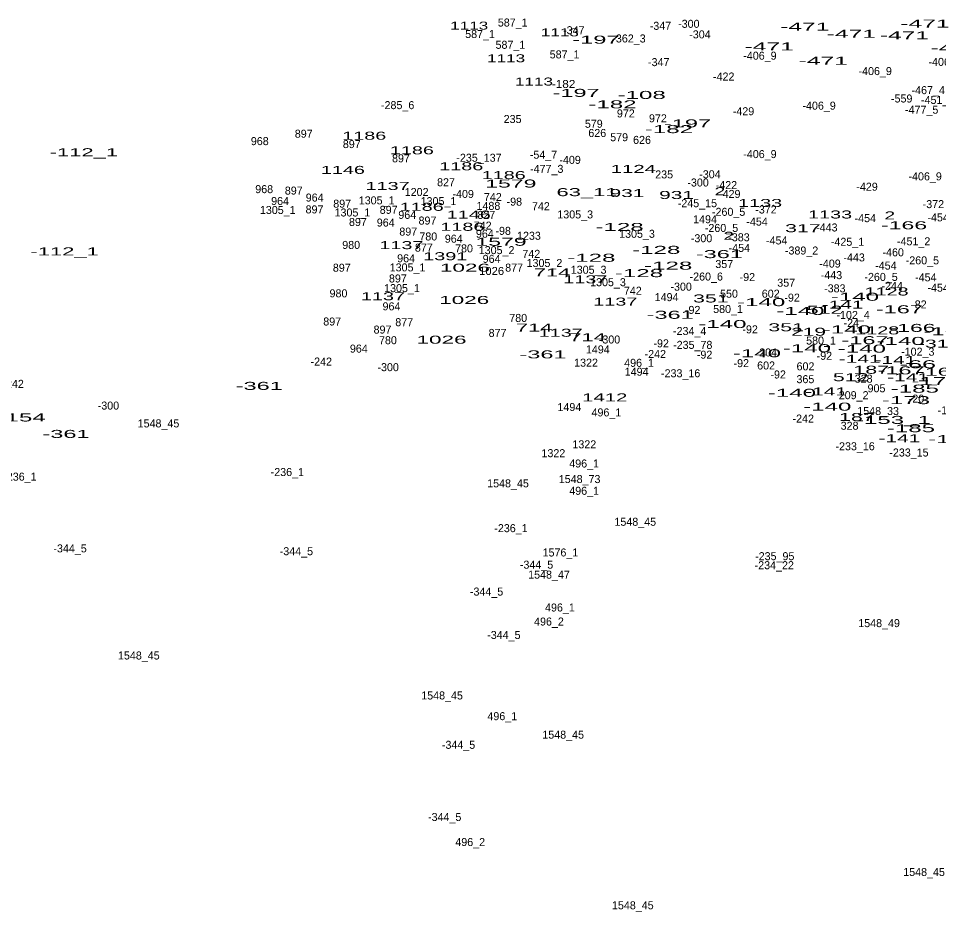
# Model space of a CAD drawing. Extents: x -660434 to -656144, y -997850 to -994016.
# Drawn here: x -659474 to -659014.2, y -996076.3 to -995629.8 of the extents above; entities that cross this region are included whole.
import ezdxf
from ezdxf.enums import TextEntityAlignment as Align

# ---------------------------------------------------------------- set-up
doc = ezdxf.new("R2010")
doc.units = 0
doc.header["$LTSCALE"] = 1.6
doc.layers.add('24', color=7, linetype='Continuous')

msp = doc.modelspace()

# ---------------------------------------------------------------- texts
at = {"layer": '24'}
for s, width, p in [('1113', 1.6, (-659248.79, -995635.4)), ('-471', 2.3, (-659081.121, -995635.93)), ('-471', 2.3, (-659021.021, -995634.39)), ('1113', 1.6, (-659203.48, -995638.76)), ('-471', 2.3, (-659057.831, -995639.5)), ('-471', 2.3, (-659031.331, -995640.26)), ('-197', 2.2, (-659185.479, -995642.42)), ('-471', 2.3, (-659098.881, -995645.83)), ('-471', 2.3, (-659005.981, -995646.6)), ('1113', 1.6, (-659230.36, -995651.72)), ('-471', 2.3, (-659071.841, -995652.94)), ('1113', 1.6, (-659216.44, -995663.35)), ('-182', 1.1, (-659201.63, -995664.56)), ('-197', 2.2, (-659195.369, -995669.02)), ('-108', 2.25, (-659162.587, -995670.05)), ('-182', 2.25, (-659177.191, -995674.74)), ('-182', 2.25, (-659148.971, -995687.12)), ('-197', 2.2, (-659139.689, -995684.28)), ('1186', 1.85, (-659301.239, -995690.43)), ('-112_1', 2.05, (-659441.334, -995698.7)), ('1186', 1.85, (-659277.429, -995697.72)), ('1146', 1.85, (-659311.905, -995707.52)), ('1186', 1.85, (-659252.759, -995705.69)), ('1186', 1.85, (-659231.539, -995710.12)), ('1124', 1.9, (-659166.759, -995707.02)), ('1579', 2.15, (-659227.997, -995714.34)), ('1137', 1.85, (-659289.579, -995715.54)), ('63_11', 2.05, (-659189.91, -995718.63)), ('931', 1.95, (-659169.943, -995719.09)), ('2', 1.8, (-659123.511, -995718.18)), ('931', 1.95, (-659145.183, -995720.05)), ('1186', 1.85, (-659272.529, -995725.97)), ('1133', 1.85, (-659103.424, -995724.04)), ('1146', 1.85, (-659249.005, -995729.84)), ('1133', 1.85, (-659068.474, -995729.8)), ('2', 1.8, (-659038.641, -995730.28)), ('1186', 1.85, (-659252.179, -995735.96)), ('-128', 2.25, (-659173.641, -995736.06)), ('317', 2, (-659082.043, -995736.65)), ('-166', 2.15, (-659031.479, -995735.21)), ('2', 1.8, (-659119.101, -995740.46)), ('1137', 1.85, (-659282.669, -995745.12)), ('1579', 2.15, (-659232.887, -995743.44)), ('-112_1', 2.05, (-659450.934, -995748.25)), ('1391', 1.85, (-659260.759, -995750.66)), ('-128', 2.25, (-659187.761, -995751.43)), ('-128', 2.25, (-659155.311, -995747.49)), ('-361', 2.2, (-659123.775, -995749.6)), ('-128', 2.25, (-659149.351, -995755.37)), ('1026', 2.1, (-659250.909, -995756.4)), ('1026', 1.05, (-659237.591, -995758.03)), ('714', 2.05, (-659207.388, -995758.78)), ('-128', 2.25, (-659163.951, -995759.11)), ('1137', 1.85, (-659190.749, -995762.21)), ('1128', 1.85, (-659040.234, -995768.29)), ('1137', 1.85, (-659291.879, -995770.66)), ('1026', 2.1, (-659251.289, -995772.53)), ('1137', 1.85, (-659175.779, -995773.35)), ('351', 2, (-659128.027, -995771.78)), ('-140', 2.25, (-659102.882, -995773.61)), ('-140', 2.25, (-659056.032, -995770.92)), ('-140', 2.25, (-659083.302, -995778.03)), ('512', 2, (-659071.197, -995777.41)), ('-141', 1.95, (-659062.202, -995774.88)), ('-167', 2.2, (-659033.809, -995777.18)), ('-361', 2.2, (-659148.345, -995779.94)), ('714', 2.05, (-659216.318, -995786.35)), ('-140', 2.25, (-659122.272, -995784.56)), ('351', 2, (-659090.397, -995786.18)), ('-140', 2.25, (-659060.062, -995787.25)), ('1128', 1.85, (-659044.894, -995787.74)), ('-166', 2.15, (-659027.249, -995786.5)), ('-163', 2.2, (-659009.915, -995788.14)), ('1026', 2.1, (-659262.619, -995792.39)), ('1137', 1.85, (-659203.039, -995788.91)), ('714', 2.05, (-659189.628, -995791.15)), ('219', 1.95, (-659079.203, -995788.42)), ('-167', 2.2, (-659050.999, -995792.64)), ('-140', 2.25, (-659080.032, -995796.66)), ('-140', 2.25, (-659052.582, -995796.85)), ('-140', 2.25, (-659033.182, -995793.01)), ('-31', 2, (-659016.931, -995794.37)), ('-361', 2.2, (-659211.905, -995799.73)), ('-140', 2.25, (-659104.992, -995799.15)), ('-141', 1.95, (-659053.662, -995801.95)), ('-141', 1.95, (-659035.802, -995802.54)), ('-66', 2.35, (-659024.583, -995804.66)), ('512', 2, (-659058.137, -995811.13)), ('187', 2, (-659047.893, -995807.41)), ('-167', 2.2, (-659032.949, -995807.72)), ('-141', 1.95, (-659029.472, -995811.17)), ('-166', 2.15, (-659013.429, -995808.39)), ('-361', 2.2, (-659353.685, -995815.48)), ('-173', 2.25, (-659015.755, -995813.08)), ('-140', 2.25, (-659087.522, -995818.94)), ('-141', 1.95, (-659070.462, -995818.28)), ('-185', 2.25, (-659026.111, -995816.84)), ('1412', 1.9, (-659181.039, -995821.24)), ('-173', 2.25, (-659030.535, -995822.59)), ('-140', 2.25, (-659069.862, -995825.85)), ('-154', 2.25, (-659472.426, -995831.25)), ('187', 2, (-659055.083, -995831.04)), ('-153_1', 2.25, (-659036.797, -995832.48)), ('-185', 2.25, (-659028.031, -995836.62)), ('-361', 2.2, (-659450.265, -995839.49)), ('-141', 1.95, (-659033.792, -995841.62)), ('-173', 2.25, (-659007.395, -995842.09))]:
    msp.add_text(s, height=4, dxfattribs=dict(at, width=width)).set_placement(p, align=Align.CENTER)
for s, p in [('587_1', (-659227.044, -995633.85)), ('-347', (-659153.215, -995635.5)), ('-300', (-659139.043, -995634.49)), ('587_1', (-659243.364, -995639.61)), ('-347', (-659196.515, -995637.7)), ('-304', (-659133.493, -995639.78)), ('587_1', (-659228.194, -995644.99)), ('-362_3', (-659168.948, -995641.82)), ('587_1', (-659201.124, -995649.79)), ('-347', (-659154.085, -995653.65)), ('-406_9', (-659103.512, -995650.44)), ('-406_9', (-659010.962, -995653.51)), ('-406_9', (-659045.912, -995658.12)), ('-422', (-659121.599, -995660.85)), ('-467_4', (-659019.422, -995667.65)), ('-559', (-659032.67, -995671.82)), ('-451_3', (-659014.7, -995672.54)), ('-285_6', (-659284.548, -995675.14)), ('-406_9', (-659073.942, -995675.41)), ('-477_5', (-659022.688, -995677.43)), ('235', (-659227.107, -995682.08)), ('972', (-659170.528, -995679.28)), ('972', (-659154.488, -995681.73)), ('-429', (-659111.725, -995678.19)), ('579', (-659186.538, -995684.45)), ('897', (-659331.468, -995689.43)), ('626', (-659184.798, -995689.06)), ('579', (-659173.868, -995691.17)), ('968', (-659353.438, -995693.13)), ('897', (-659307.468, -995694.62)), ('626', (-659162.428, -995692.52)), ('-54_7', (-659211.652, -995699.92)), ('-406_9', (-659103.512, -995699.61)), ('897', (-659282.888, -995701.73)), ('-235_137', (-659243.911, -995701.44)), ('-409', (-659198.379, -995702.5)), ('-477_3', (-659210.048, -995707)), ('235', (-659151.367, -995709.77)), ('-304', (-659128.503, -995709.7)), ('827', (-659260.373, -995713.68)), ('-300', (-659134.423, -995713.82)), ('-406_9', (-659020.952, -995710.75)), ('968', (-659351.238, -995717.14)), ('897', (-659336.458, -995717.86)), ('1202', (-659275.054, -995718.58)), ('-422', (-659120.259, -995715.1)), ('-429', (-659049.985, -995715.93)), ('964', (-659343.303, -995723.08)), ('964', (-659326.023, -995721.35)), ('1305_1', (-659295.046, -995722.75)), ('1305_1', (-659264.136, -995723.14)), ('-409', (-659251.799, -995719.55)), ('742', (-659236.967, -995721.06)), ('-98', (-659226.24, -995723.39)), ('-429', (-659118.585, -995719.53)), ('1305_1', (-659344.456, -995727.55)), ('897', (-659326.088, -995727.27)), ('897', (-659312.268, -995724.39)), ('897', (-659289.038, -995727.47)), ('1488', (-659239.194, -995725.5)), ('742', (-659212.967, -995725.67)), ('-245_15', (-659134.759, -995724.16)), ('-260_5', (-659119.152, -995728.47)), ('-372', (-659100.501, -995727.31)), ('-372', (-659016.841, -995724.62)), ('1305_1', (-659307.136, -995728.8)), ('964', (-659279.743, -995730)), ('897', (-659269.638, -995732.84)), ('827', (-659240.213, -995730)), ('1305_3', (-659195.833, -995729.77)), ('1494', (-659130.954, -995732.18)), ('-454', (-659050.853, -995731.63)), ('-454', (-659014.463, -995731.25)), ('897', (-659304.398, -995733.55)), ('964', (-659290.503, -995733.84)), ('742', (-659242.057, -995735.37)), ('-260_5', (-659122.712, -995736.53)), ('-454', (-659104.953, -995733.36)), ('-443', (-659070.083, -995736.29)), ('897', (-659279.238, -995738.35)), ('780', (-659269.237, -995740.79)), ('964', (-659256.513, -995741.91)), ('964', (-659240.963, -995739.41)), ('-98', (-659231.81, -995737.99)), ('1233', (-659218.94, -995740.44)), ('1305_3', (-659164.943, -995739.45)), ('-300', (-659132.693, -995741.68)), ('-383', (-659113.985, -995741.19)), ('980', (-659307.777, -995745.02)), ('877', (-659271.469, -995746.37)), ('780', (-659251.377, -995746.74)), ('-454', (-659113.793, -995746.52)), ('-454', (-659095.133, -995742.78)), ('-425_1', (-659059.73, -995743.45)), ('-451_2', (-659026.7, -995743.21)), ('1305_2', (-659235.093, -995747.63)), ('742', (-659217.757, -995749.49)), ('-389_2', (-659082.698, -995747.81)), ('-443', (-659056.453, -995751.27)), ('-460', (-659036.919, -995748.7)), ('964', (-659280.323, -995751.7)), ('964', (-659237.603, -995751.99)), ('1305_2', (-659211.193, -995754.06)), ('357', (-659121.333, -995754.56)), ('-409', (-659068.499, -995754.34)), ('-454', (-659040.573, -995755.35)), ('-260_5', (-659022.342, -995752.73)), ('897', (-659312.458, -995756.41)), ('1305_1', (-659279.596, -995756.25)), ('877', (-659226.349, -995756.36)), ('1305_3', (-659189.113, -995757.42)), ('-443', (-659067.783, -995760.11)), ('897', (-659284.428, -995761.79)), ('1305_3', (-659179.443, -995763.65)), ('-260_6', (-659130.337, -995760.83)), ('-92', (-659109.8, -995761.08)), ('357', (-659090.393, -995763.9)), ('-260_5', (-659042.982, -995761)), ('-454', (-659020.633, -995761.22)), ('980', (-659314.107, -995769.22)), ('1305_1', (-659282.376, -995766.62)), ('742', (-659167.027, -995767.91)), ('-300', (-659142.873, -995765.88)), ('550', (-659118.971, -995769.4)), ('602', (-659098.127, -995769.39)), ('-383', (-659066.095, -995766.74)), ('-244', (-659037.433, -995765.47)), ('-454', (-659014.463, -995766.4)), ('1494', (-659150.154, -995771.12)), ('-92', (-659087.43, -995771.36)), ('964', (-659287.623, -995775.71)), ('-92', (-659137.12, -995777.51)), ('580_1', (-659119.453, -995777.06)), ('82', (-659023.177, -995774.78)), ('897', (-659317.258, -995783.3)), ('877', (-659281.259, -995783.64)), ('780', (-659224.307, -995781.51)), ('-102_4', (-659056.944, -995780.02)), ('897', (-659292.108, -995787.33)), ('-234_4', (-659138.621, -995788.05)), ('-92', (-659108.41, -995787.21)), ('-24', (-659057.839, -995783.98)), ('780', (-659289.397, -995792.65)), ('877', (-659234.609, -995789.01)), ('-300', (-659178.683, -995792.29)), ('580_1', (-659072.983, -995792.81)), ('964', (-659303.943, -995796.84)), ('1494', (-659184.524, -995797.24)), ('-92', (-659152.86, -995794.22)), ('-235_78', (-659137.087, -995794.97)), ('-242', (-659155.789, -995799.54)), ('-92', (-659131.17, -995799.88)), ('204', (-659099.425, -995798.76)), ('-92', (-659071.3, -995800.44)), ('-102_3', (-659024.64, -995798.39)), ('-242', (-659322.699, -995803.32)), ('-300', (-659289.283, -995806.12)), ('1322', (-659190.41, -995803.88)), ('496_1', (-659163.904, -995803.95)), ('-92', (-659112.83, -995804.11)), ('602', (-659100.437, -995805.28)), ('602', (-659080.747, -995805.71)), ('1494', (-659165.124, -995808.38)), ('-233_16', (-659143.121, -995809.17)), ('-92', (-659094.4, -995809.77)), ('-242', (-659476.689, -995814.46)), ('365', (-659080.793, -995812.12)), ('328', (-659051.707, -995811.87)), ('209_2', (-659056.674, -995820.13)), ('905', (-659045.267, -995816.67)), ('-20', (-659025.279, -995821.85)), ('-300', (-659429.063, -995825.32)), ('1494', (-659198.734, -995826.05)), ('496_1', (-659180.224, -995828.73)), ('1548_33', (-659044.452, -995828.05)), ('-102_2', (-659006.41, -995827.71)), ('1548_45', (-659404.047, -995834.23)), ('-242', (-659081.869, -995831.81)), ('328', (-659058.717, -995835.4)), ('1322', (-659191.27, -995844.69)), ('-233_16', (-659055.951, -995845.66)), ('1322', (-659206.73, -995849.11)), ('-233_15', (-659029.045, -995848.78)), ('496_1', (-659191.354, -995854.27)), ('-236_1', (-659473.302, -995860.85)), ('-236_1', (-659339.662, -995858.54)), ('1548_45', (-659229.397, -995864.19)), ('1548_73', (-659193.617, -995862.05)), ('496_1', (-659191.354, -995867.91)), ('1548_45', (-659165.807, -995883.4)), ('-236_1', (-659227.912, -995886.59)), ('-344_5', (-659448.231, -995896.71)), ('-344_5', (-659335.141, -995898.12)), ('1576_1', (-659203.204, -995898.74)), ('-235_95', (-659096.107, -995900.6)), ('-344_5', (-659215.141, -995904.84)), ('-234_22', (-659096.346, -995905.11)), ('1548_47', (-659208.912, -995909.83)), ('-344_5', (-659240.101, -995918.29)), ('496_1', (-659203.454, -995926.25)), ('496_2', (-659208.93, -995933.27)), ('1548_49', (-659043.972, -995934.06)), ('-344_5', (-659231.461, -995939.98)), ('1548_45', (-659413.877, -995950.24)), ('1548_45', (-659262.347, -995970.22)), ('496_1', (-659232.254, -995980.57)), ('1548_45', (-659201.827, -995989.81)), ('-344_5', (-659254.111, -995994.89)), ('-344_5', (-659261.031, -996030.96)), ('496_2', (-659248.29, -996043.49)), ('1548_45', (-659021.497, -996058.46)), ('1548_45', (-659167.027, -996075.1))]:
    msp.add_text(s, height=4, dxfattribs=at).set_placement(p, align=Align.CENTER)

doc.saveas('drawing.dxf')
